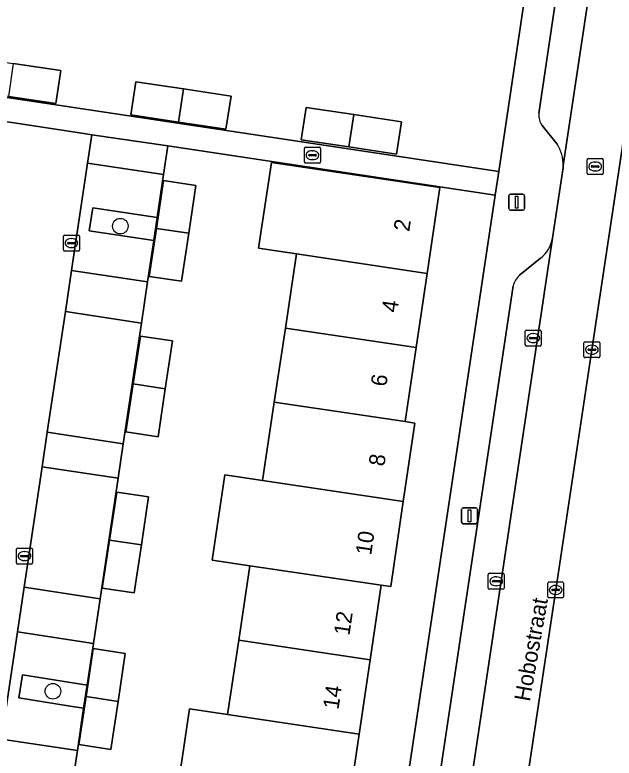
# Model space of a CAD drawing. Extents: x 164148 to 165261, y 382513 to 383432.
# Drawn here: x 164347.95 to 164385.58, y 382801.38 to 382848.02 of the extents above; entities that cross this region are included whole.
import ezdxf

# ---------------------------------------------------------------- set-up
doc = ezdxf.new("R2010")
doc.units = 0
for name, color, linetype in [('IMGEO_Boom', 7, 'Continuous'), ('IMGEO_Erf', 7, 'Continuous'), ('IMGEO_Groenvoorziening', 7, 'Continuous'), ('IMGEO_Kolk', 7, 'Continuous'), ('IMGEO_Lichtmast', 7, 'Continuous'), ('IMGEO_Openbare_ruimte_label', 7, 'Continuous'), ('IMGEO_Pand', 7, 'Continuous'), ('IMGEO_Pand_nummerreeks', 7, 'Continuous'), ('IMGEO_Parkeervlak_open', 7, 'Continuous'), ('IMGEO_Rijbaan_lokaal_open', 7, 'Continuous'), ('IMGEO_Rioolput', 7, 'Continuous'), ('IMGEO_Voetpad_open', 7, 'Continuous')]:
    doc.layers.add(name, color=color, linetype=linetype)

msp = doc.modelspace()

# ---------------------------------------------------------------- linework, layer by layer
at = {"layer": 'IMGEO_Boom'}
for centre in [(164354.574, 382834.763), (164350.346, 382805.576)]:
    msp.add_circle(centre, 0.489, dxfattribs=at)
at = {"layer": 'IMGEO_Erf'}
for points in [[(164380.889, 382859.124), (164325.776, 382867.343), (164325.126, 382866.898), (164322.133, 382846.618), (164350.25, 382842.417), (164378.331, 382838.195), (164381.369, 382858.602)], [(164350.836, 382844.524), (164350.517, 382842.454), (164347.545, 382842.897), (164344.545, 382843.344), (164344.866, 382845.407), (164347.851, 382844.966)], [(164358.537, 382843.372), (164361.525, 382842.923), (164361.208, 382840.852), (164358.225, 382841.297), (164355.24, 382841.743), (164355.548, 382843.82)], [(164369.229, 382841.763), (164372.219, 382841.312), (164371.913, 382839.285), (164368.923, 382839.736), (164365.932, 382840.187), (164366.238, 382842.214)], [(164356.395, 382831.608), (164356.846, 382834.625), (164357.294, 382837.621), (164359.324, 382837.325), (164358.868, 382834.319), (164358.411, 382831.312)], [(164354.92, 382821.853), (164355.381, 382824.867), (164355.84, 382827.87), (164357.858, 382827.572), (164357.4, 382824.56), (164356.942, 382821.548)], [(164353.44, 382812.046), (164353.894, 382815.063), (164354.347, 382818.074), (164356.353, 382817.767), (164355.903, 382814.762), (164355.453, 382811.757)], [(164351.964, 382802.238), (164352.421, 382805.243), (164352.878, 382808.248), (164354.887, 382807.937), (164354.43, 382804.937), (164353.971, 382801.923)]]:
    msp.add_lwpolyline(points, close=True, dxfattribs=at)
for points in [[(164364.8, 382747.97), (164378.11, 382836.71), (164357.562, 382839.799), (164357.294, 382838.011), (164356.888, 382835.303), (164356.672, 382833.86), (164356.285, 382831.275), (164355.896, 382828.681), (164354.761, 382821.108), (164354.436, 382818.942), (164353.301, 382811.365), (164352.883, 382808.572), (164352.49, 382805.954), (164352.274, 382804.514), (164351.878, 382801.866), (164351.47, 382799.147)], [(164358.116, 382799.103), (164358.921, 382804.468), (164361.307, 382804.11), (164362.007, 382808.775), (164362.706, 382813.439), (164360.331, 382813.796), (164361.136, 382819.166), (164363.508, 382818.81), (164364.243, 382823.711), (164364.941, 382828.365), (164365.64, 382833.027), (164363.251, 382833.385), (164364.056, 382838.755), (164374.643, 382837.187), (164373.845, 382831.798), (164373.156, 382827.148), (164372.467, 382822.499), (164373.071, 382822.41), (164372.341, 382817.484), (164371.55, 382812.142), (164370.946, 382812.231), (164370.251, 382807.538), (164369.56, 382802.872), (164368.765, 382797.504)]]:
    msp.add_lwpolyline(points, dxfattribs=at)
at = {"layer": 'IMGEO_Groenvoorziening'}
msp.add_lwpolyline([(164388.653, 382856.791), (164388.469, 382855.564), (164387.957, 382852.16), (164384.178, 382827.011), (164381.905, 382811.932), (164379.997, 382799.194), (164379.527, 382795.989), (164377.081, 382779.734), (164374.497, 382762.461), (164372.688, 382750.223), (164377.348, 382749.559)], dxfattribs=at)
for points in [[(164356.888, 382835.303), (164352.851, 382835.923), (164352.609, 382834.466), (164356.672, 382833.86)], [(164352.49, 382805.954), (164348.44, 382806.605), (164348.214, 382805.152), (164351.421, 382804.648), (164352.274, 382804.514)]]:
    msp.add_lwpolyline(points, close=True, dxfattribs=at)
at = {"layer": 'IMGEO_Kolk'}
for p, q in [((164366.213, 382839.717), (164367.065, 382839.717)), ((164366.138, 382838.791), (164366.138, 382839.643)), ((164366.397, 382839.211), (164366.397, 382839.223)), ((164366.44, 382839.26), (164366.838, 382839.26)), ((164366.626, 382839.497), (164366.651, 382839.497)), ((164366.881, 382839.223), (164366.881, 382839.211)), ((164367.139, 382839.643), (164367.139, 382838.791)), ((164366.835, 382839.174), (164366.437, 382839.174)), ((164366.649, 382838.937), (164366.624, 382838.937)), ((164367.065, 382838.717), (164366.213, 382838.717)), ((164351.003, 382833.274), (164351.003, 382834.126)), ((164351.078, 382834.2), (164351.93, 382834.2)), ((164352.004, 382834.126), (164352.004, 382833.274)), ((164351.262, 382833.694), (164351.262, 382833.706)), ((164351.7, 382833.657), (164351.302, 382833.657)), ((164351.305, 382833.743), (164351.703, 382833.743)), ((164351.491, 382833.98), (164351.516, 382833.98)), ((164351.746, 382833.706), (164351.746, 382833.694)), ((164351.93, 382833.2), (164351.078, 382833.2)), ((164351.514, 382833.42), (164351.489, 382833.42)), ((164379.999, 382827.315), (164379.999, 382828.167)), ((164380.074, 382828.241), (164380.926, 382828.241)), ((164380.487, 382828.021), (164380.512, 382828.021)), ((164381, 382828.167), (164381, 382827.315)), ((164380.258, 382827.735), (164380.258, 382827.747)), ((164380.696, 382827.698), (164380.298, 382827.698)), ((164380.301, 382827.784), (164380.699, 382827.784)), ((164380.742, 382827.747), (164380.742, 382827.735)), ((164380.926, 382827.241), (164380.074, 382827.241)), ((164380.51, 382827.461), (164380.485, 382827.461)), ((164383.677, 382826.585), (164383.677, 382827.437)), ((164383.752, 382827.511), (164384.604, 382827.511)), ((164384.165, 382827.291), (164384.19, 382827.291)), ((164384.678, 382827.437), (164384.678, 382826.585)), ((164383.936, 382827.005), (164383.936, 382827.017)), ((164384.374, 382826.968), (164383.976, 382826.968)), ((164383.979, 382827.054), (164384.377, 382827.054)), ((164384.188, 382826.731), (164384.163, 382826.731)), ((164384.42, 382827.017), (164384.42, 382827.005)), ((164384.604, 382826.511), (164383.752, 382826.511)), ((164348.058, 382813.633), (164348.058, 382814.485)), ((164348.133, 382814.559), (164348.985, 382814.559)), ((164349.059, 382814.485), (164349.059, 382813.633)), ((164348.317, 382814.053), (164348.317, 382814.065)), ((164348.755, 382814.016), (164348.357, 382814.016)), ((164348.36, 382814.102), (164348.758, 382814.102)), ((164348.546, 382814.339), (164348.571, 382814.339)), ((164348.801, 382814.065), (164348.801, 382814.053)), ((164348.985, 382813.559), (164348.133, 382813.559)), ((164348.569, 382813.779), (164348.544, 382813.779)), ((164377.671, 382812.05), (164377.671, 382812.902)), ((164377.746, 382812.976), (164378.598, 382812.976)), ((164378.159, 382812.756), (164378.184, 382812.756)), ((164378.672, 382812.902), (164378.672, 382812.05)), ((164377.93, 382812.47), (164377.93, 382812.482)), ((164378.368, 382812.433), (164377.97, 382812.433)), ((164377.973, 382812.519), (164378.371, 382812.519)), ((164378.182, 382812.196), (164378.157, 382812.196)), ((164378.414, 382812.482), (164378.414, 382812.47)), ((164381.404, 382811.506), (164381.404, 382812.358)), ((164381.479, 382812.432), (164382.331, 382812.432)), ((164381.892, 382812.212), (164381.917, 382812.212)), ((164382.405, 382812.358), (164382.405, 382811.506)), ((164378.598, 382811.976), (164377.746, 382811.976)), ((164381.663, 382811.926), (164381.663, 382811.938)), ((164382.101, 382811.889), (164381.703, 382811.889)), ((164381.706, 382811.975), (164382.104, 382811.975)), ((164382.147, 382811.938), (164382.147, 382811.926)), ((164382.331, 382811.432), (164381.479, 382811.432)), ((164381.915, 382811.652), (164381.89, 382811.652))]:
    msp.add_line(p, q, dxfattribs=at)
for points in [[(164366.213, 382839.717), (164367.065, 382839.717)], [(164366.138, 382838.791), (164366.138, 382839.643)], [(164367.139, 382839.643), (164367.139, 382838.791)], [(164367.065, 382838.717), (164366.213, 382838.717)], [(164351.003, 382833.274), (164351.003, 382834.126)], [(164351.078, 382834.2), (164351.93, 382834.2)], [(164352.004, 382834.126), (164352.004, 382833.274)], [(164351.93, 382833.2), (164351.078, 382833.2)], [(164379.999, 382827.315), (164379.999, 382828.167)], [(164380.074, 382828.241), (164380.926, 382828.241)], [(164381, 382828.167), (164381, 382827.315)], [(164380.926, 382827.241), (164380.074, 382827.241)], [(164383.677, 382826.585), (164383.677, 382827.437)], [(164383.752, 382827.511), (164384.604, 382827.511)], [(164384.678, 382827.437), (164384.678, 382826.585)], [(164384.604, 382826.511), (164383.752, 382826.511)], [(164348.058, 382813.633), (164348.058, 382814.485)], [(164348.133, 382814.559), (164348.985, 382814.559)], [(164349.059, 382814.485), (164349.059, 382813.633)], [(164348.985, 382813.559), (164348.133, 382813.559)], [(164377.671, 382812.05), (164377.671, 382812.902)], [(164377.746, 382812.976), (164378.598, 382812.976)], [(164378.672, 382812.902), (164378.672, 382812.05)], [(164381.404, 382811.506), (164381.404, 382812.358)], [(164381.479, 382812.432), (164382.331, 382812.432)], [(164382.405, 382812.358), (164382.405, 382811.506)], [(164378.598, 382811.976), (164377.746, 382811.976)], [(164382.331, 382811.432), (164381.479, 382811.432)]]:
    msp.add_lwpolyline(points, dxfattribs=at)
for centre, radius, start, end in [((164366.215, 382839.641), 0.0765, 91.552, 178.448), ((164366.215, 382839.641), 0.0765, 91.552, 178.448), ((164367.063, 382839.641), 0.0765, 1.552, 88.448), ((164367.063, 382839.641), 0.0765, 1.552, 88.448), ((164366.437, 382839.22), 0.0403, 85.8775, 175.7526), ((164366.434, 382839.21), 0.0366, 178.938, 274.7102), ((164366.838, 382839.217), 0.043, 264.8664, 352.4533), ((164366.842, 382839.222), 0.0386, 1.7309, 96.639), ((164366.215, 382838.793), 0.0765, 181.552, 268.448), ((164366.215, 382838.793), 0.0765, 181.552, 268.448), ((164367.063, 382838.793), 0.0765, 271.552, 358.448), ((164367.063, 382838.793), 0.0765, 271.552, 358.448), ((164351.08, 382834.124), 0.0765, 91.552, 178.448), ((164351.08, 382834.124), 0.0765, 91.552, 178.448), ((164351.928, 382834.124), 0.0765, 1.552, 88.448), ((164351.928, 382834.124), 0.0765, 1.552, 88.448), ((164351.302, 382833.703), 0.0403, 85.8775, 175.7526), ((164351.299, 382833.693), 0.0366, 178.938, 274.7102), ((164351.703, 382833.7), 0.043, 264.8664, 352.4533), ((164351.707, 382833.705), 0.0386, 1.7309, 96.639), ((164351.08, 382833.276), 0.0765, 181.552, 268.448), ((164351.08, 382833.276), 0.0765, 181.552, 268.448), ((164351.928, 382833.276), 0.0765, 271.552, 358.448), ((164351.928, 382833.276), 0.0765, 271.552, 358.448), ((164380.076, 382828.165), 0.0765, 91.552, 178.448), ((164380.076, 382828.165), 0.0765, 91.552, 178.448), ((164380.924, 382828.165), 0.0765, 1.552, 88.448), ((164380.924, 382828.165), 0.0765, 1.552, 88.448), ((164380.298, 382827.744), 0.0403, 85.8775, 175.7526), ((164380.295, 382827.734), 0.0366, 178.938, 274.7102), ((164380.699, 382827.741), 0.043, 264.8664, 352.4533), ((164380.703, 382827.746), 0.0386, 1.7309, 96.639), ((164380.076, 382827.317), 0.0765, 181.552, 268.448), ((164380.076, 382827.317), 0.0765, 181.552, 268.448), ((164380.924, 382827.317), 0.0765, 271.552, 358.448), ((164380.924, 382827.317), 0.0765, 271.552, 358.448), ((164383.754, 382827.435), 0.0765, 91.552, 178.448), ((164383.754, 382827.435), 0.0765, 91.552, 178.448), ((164384.602, 382827.435), 0.0765, 1.552, 88.448), ((164384.602, 382827.435), 0.0765, 1.552, 88.448), ((164383.976, 382827.014), 0.0403, 85.8775, 175.7526), ((164383.973, 382827.004), 0.0366, 178.938, 274.7102), ((164384.377, 382827.011), 0.043, 264.8664, 352.4533), ((164384.381, 382827.016), 0.0386, 1.7309, 96.639), ((164383.754, 382826.587), 0.0765, 181.552, 268.448), ((164383.754, 382826.587), 0.0765, 181.552, 268.448), ((164384.602, 382826.587), 0.0765, 271.552, 358.448), ((164384.602, 382826.587), 0.0765, 271.552, 358.448), ((164348.135, 382814.483), 0.0765, 91.552, 178.448), ((164348.135, 382814.483), 0.0765, 91.552, 178.448), ((164348.983, 382814.483), 0.0765, 1.552, 88.448), ((164348.983, 382814.483), 0.0765, 1.552, 88.448), ((164348.357, 382814.062), 0.0403, 85.8775, 175.7526), ((164348.354, 382814.052), 0.0366, 178.938, 274.7102), ((164348.758, 382814.059), 0.043, 264.8664, 352.4533), ((164348.762, 382814.064), 0.0386, 1.7309, 96.639), ((164348.135, 382813.635), 0.0765, 181.552, 268.448), ((164348.135, 382813.635), 0.0765, 181.552, 268.448), ((164348.983, 382813.635), 0.0765, 271.552, 358.448), ((164348.983, 382813.635), 0.0765, 271.552, 358.448), ((164377.748, 382812.9), 0.0765, 91.552, 178.448), ((164377.748, 382812.9), 0.0765, 91.552, 178.448), ((164378.596, 382812.9), 0.0765, 1.552, 88.448), ((164378.596, 382812.9), 0.0765, 1.552, 88.448), ((164377.97, 382812.479), 0.0403, 85.8775, 175.7526), ((164377.967, 382812.469), 0.0366, 178.938, 274.7102), ((164378.371, 382812.476), 0.043, 264.8664, 352.4533), ((164378.375, 382812.481), 0.0386, 1.7309, 96.639), ((164381.481, 382812.356), 0.0765, 91.552, 178.448), ((164381.481, 382812.356), 0.0765, 91.552, 178.448), ((164382.329, 382812.356), 0.0765, 1.552, 88.448), ((164382.329, 382812.356), 0.0765, 1.552, 88.448), ((164377.748, 382812.052), 0.0765, 181.552, 268.448), ((164377.748, 382812.052), 0.0765, 181.552, 268.448), ((164378.596, 382812.052), 0.0765, 271.552, 358.448), ((164378.596, 382812.052), 0.0765, 271.552, 358.448), ((164381.703, 382811.935), 0.0403, 85.8775, 175.7526), ((164381.7, 382811.925), 0.0366, 178.938, 274.7102), ((164382.104, 382811.932), 0.043, 264.8664, 352.4533), ((164382.108, 382811.937), 0.0386, 1.7309, 96.639), ((164381.481, 382811.508), 0.0765, 181.552, 268.448), ((164381.481, 382811.508), 0.0765, 181.552, 268.448), ((164382.329, 382811.508), 0.0765, 271.552, 358.448), ((164382.329, 382811.508), 0.0765, 271.552, 358.448)]:
    msp.add_arc(centre, radius, start, end, dxfattribs=at)
for centre, major_axis, ratio, start_param, end_param in [((164366.625, 382839.217), (-0.387, 0.002), 0.722429, 4.712389, 7.853982), ((164366.65, 382839.217), (-0.39, 0.002), 0.717154, 1.570796, 4.712389), ((164351.49, 382833.7), (-0.387, 0.002), 0.722429, 4.712389, 7.853982), ((164351.515, 382833.7), (-0.39, 0.002), 0.717154, 1.570796, 4.712389), ((164380.486, 382827.741), (-0.387, 0.002), 0.722429, 4.712389, 7.853982), ((164380.511, 382827.741), (-0.39, 0.002), 0.717154, 1.570796, 4.712389), ((164384.164, 382827.011), (-0.387, 0.002), 0.722429, 4.712389, 7.853982), ((164384.189, 382827.011), (-0.39, 0.002), 0.717154, 1.570796, 4.712389), ((164348.545, 382814.059), (-0.387, 0.002), 0.722429, 4.712389, 7.853982), ((164348.57, 382814.059), (-0.39, 0.002), 0.717154, 1.570796, 4.712389), ((164378.158, 382812.476), (-0.387, 0.002), 0.722429, 4.712389, 7.853982), ((164378.183, 382812.476), (-0.39, 0.002), 0.717154, 1.570796, 4.712389), ((164381.891, 382811.932), (-0.387, 0.002), 0.722429, 4.712389, 7.853982), ((164381.916, 382811.932), (-0.39, 0.002), 0.717154, 1.570796, 4.712389)]:
    msp.add_ellipse(centre, major_axis=major_axis, ratio=ratio, start_param=start_param, end_param=end_param, dxfattribs=at)
at = {"layer": 'IMGEO_Lichtmast'}
for p, q in [((164378.962, 382835.862), (164378.962, 382836.662)), ((164378.962, 382836.662), (164378.962, 382835.862)), ((164379.062, 382836.762), (164379.852, 382836.762)), ((164379.852, 382836.762), (164379.062, 382836.762)), ((164379.952, 382836.662), (164379.952, 382835.862)), ((164379.952, 382835.862), (164379.952, 382836.662)), ((164379.852, 382835.762), (164379.062, 382835.762)), ((164379.062, 382835.762), (164379.852, 382835.762)), ((164375.999, 382816.187), (164375.999, 382816.987)), ((164375.999, 382816.987), (164375.999, 382816.187)), ((164376.099, 382817.087), (164376.889, 382817.087)), ((164376.889, 382817.087), (164376.099, 382817.087)), ((164376.989, 382816.987), (164376.989, 382816.187)), ((164376.989, 382816.187), (164376.989, 382816.987)), ((164376.889, 382816.087), (164376.099, 382816.087)), ((164376.099, 382816.087), (164376.889, 382816.087))]:
    msp.add_line(p, q, dxfattribs=at)
for points in [[(164379.382, 382836.637), (164379.532, 382836.637), (164379.532, 382835.887), (164379.382, 382835.887), (164379.382, 382836.637)], [(164376.419, 382816.962), (164376.569, 382816.962), (164376.569, 382816.212), (164376.419, 382816.212), (164376.419, 382816.962)]]:
    msp.add_lwpolyline(points, dxfattribs=at)
for centre, start, end in [((164379.062, 382836.662), 90, 180), ((164379.062, 382836.662), 90, 180), ((164379.852, 382836.662), 0, 90), ((164379.852, 382836.662), 360, 90), ((164379.062, 382835.862), 180, 270), ((164379.062, 382835.862), 180, 270), ((164379.852, 382835.862), 270, 0), ((164379.852, 382835.862), 270, 0), ((164376.099, 382816.987), 90, 180), ((164376.099, 382816.987), 90, 180), ((164376.889, 382816.987), 0, 90), ((164376.889, 382816.987), 360, 90), ((164376.099, 382816.187), 180, 270), ((164376.099, 382816.187), 180, 270), ((164376.889, 382816.187), 270, 0), ((164376.889, 382816.187), 270, 0)]:
    msp.add_arc(centre, 0.1, start, end, dxfattribs=at)
at = {"layer": 'IMGEO_Pand'}
for points in [[(164350.836, 382844.524), (164347.851, 382844.966), (164347.545, 382842.897), (164350.517, 382842.454)], [(164358.537, 382843.372), (164355.548, 382843.82), (164355.24, 382841.743), (164358.225, 382841.297)], [(164361.525, 382842.923), (164358.537, 382843.372), (164358.225, 382841.297), (164361.208, 382840.852)], [(164369.229, 382841.763), (164366.238, 382842.214), (164365.932, 382840.187), (164368.923, 382839.736)], [(164372.219, 382841.312), (164369.229, 382841.763), (164368.923, 382839.736), (164371.913, 382839.285)], [(164374.643, 382837.187), (164364.056, 382838.755), (164363.251, 382833.385), (164365.64, 382833.027), (164373.845, 382831.798)], [(164359.324, 382837.325), (164357.294, 382837.621), (164356.846, 382834.625), (164358.868, 382834.319)], [(164358.868, 382834.319), (164356.846, 382834.625), (164356.395, 382831.608), (164358.411, 382831.312)], [(164373.845, 382831.798), (164365.64, 382833.027), (164364.941, 382828.365), (164373.156, 382827.148)], [(164373.156, 382827.148), (164364.941, 382828.365), (164364.243, 382823.711), (164372.467, 382822.499)], [(164357.858, 382827.572), (164355.84, 382827.87), (164355.381, 382824.867), (164357.4, 382824.56)], [(164357.4, 382824.56), (164355.381, 382824.867), (164354.92, 382821.853), (164356.942, 382821.548)], [(164373.071, 382822.41), (164372.467, 382822.499), (164364.243, 382823.711), (164363.508, 382818.81), (164372.341, 382817.484)], [(164372.341, 382817.484), (164363.508, 382818.81), (164361.136, 382819.166), (164360.331, 382813.796), (164362.706, 382813.439), (164370.946, 382812.231), (164371.55, 382812.142)], [(164356.353, 382817.767), (164354.347, 382818.074), (164353.894, 382815.063), (164355.903, 382814.762)], [(164355.903, 382814.762), (164353.894, 382815.063), (164353.44, 382812.046), (164355.453, 382811.757)], [(164370.946, 382812.231), (164362.706, 382813.439), (164362.007, 382808.775), (164370.251, 382807.538)], [(164370.251, 382807.538), (164362.007, 382808.775), (164361.307, 382804.11), (164369.56, 382802.872)], [(164352.878, 382808.248), (164352.421, 382805.243), (164354.43, 382804.937), (164354.887, 382807.937)], [(164354.43, 382804.937), (164352.421, 382805.243), (164351.964, 382802.238), (164353.971, 382801.923)], [(164369.56, 382802.872), (164361.307, 382804.11), (164358.921, 382804.468), (164358.116, 382799.103), (164360.493, 382798.746), (164368.765, 382797.504)]]:
    msp.add_lwpolyline(points, close=True, dxfattribs=at)
at = {"layer": 'IMGEO_Parkeervlak_open'}
for points in [[(164382.377, 382838.563), (164385.018, 382856.097)], [(164382.615, 382853.697), (164380.849, 382841.827)], [(164381.049, 382841.077), (164381.999, 382839.912)], [(164377.452, 382805.647), (164381.703, 382834.004)], [(164380.962, 382832.756), (164379.639, 382831.691)], [(164379.235, 382831.014), (164367.98, 382755.927)], [(164369.459, 382752.322), (164377.452, 382805.647)]]:
    msp.add_lwpolyline(points, dxfattribs=at)
for points in [[(164356.672, 382833.86), (164352.609, 382834.466), (164352.851, 382835.923), (164356.888, 382835.303), (164357.294, 382838.011), (164352.523, 382838.717), (164351.515, 382831.984), (164356.285, 382831.275)], [(164355.896, 382828.681), (164351.128, 382829.402), (164349.993, 382821.825), (164354.761, 382821.108)], [(164354.436, 382818.942), (164349.669, 382819.657), (164348.538, 382812.111), (164353.301, 382811.365)], [(164352.274, 382804.514), (164351.421, 382804.648), (164348.214, 382805.152), (164348.44, 382806.605), (164352.49, 382805.954), (164352.883, 382808.572), (164348.119, 382809.31), (164347.108, 382802.559), (164351.878, 382801.866)]]:
    msp.add_lwpolyline(points, close=True, dxfattribs=at)
for centre, radius, start, end in [((164381.95, 382841.719), 1.107, 174.4014, 215.4614), ((164380.071, 382838.644), 2.307, 357.9806, 33.3259), ((164379.679, 382834.362), 2.055, 308.6221, 349.9784), ((164380.647, 382830.631), 1.463, 133.542, 164.8047)]:
    msp.add_arc(centre, radius, start, end, dxfattribs=at)
at = {"layer": 'IMGEO_Rijbaan_lokaal_open'}
msp.add_lwpolyline([(164377.081, 382779.734), (164379.527, 382795.989), (164379.997, 382799.194), (164381.905, 382811.932), (164384.178, 382827.011), (164387.957, 382852.16), (164388.469, 382855.564), (164385.018, 382856.097), (164382.377, 382838.563), (164382.368, 382838.422), (164382.245, 382837.606), (164381.703, 382834.004), (164377.452, 382805.647), (164369.459, 382752.322), (164369.209, 382750.719), (164372.688, 382750.223), (164374.497, 382762.461)], close=True, dxfattribs=at)
msp.add_lwpolyline([(164346.706, 382799.875), (164347.108, 382802.559), (164348.119, 382809.31), (164348.538, 382812.111), (164349.669, 382819.657), (164349.993, 382821.825), (164351.128, 382829.402), (164351.515, 382831.984), (164352.523, 382838.717), (164352.791, 382840.504), (164352.276, 382840.585), (164347.755, 382841.26), (164347.238, 382841.326), (164347.039, 382839.997), (164345.904, 382832.423), (164345.486, 382829.632), (164344.474, 382822.879), (164344.073, 382820.206), (164342.967, 382812.827), (164342.629, 382810.568), (164341.49, 382802.969), (164341.089, 382800.293)], dxfattribs=at)
at = {"layer": 'IMGEO_Rioolput'}
for p, q in [((164383.884, 382838.084), (164383.884, 382838.936)), ((164383.959, 382839.01), (164384.811, 382839.01)), ((164384.372, 382838.79), (164384.397, 382838.79)), ((164384.885, 382838.936), (164384.885, 382838.084)), ((164384.143, 382838.504), (164384.143, 382838.516)), ((164384.581, 382838.467), (164384.183, 382838.467)), ((164384.186, 382838.553), (164384.584, 382838.553)), ((164384.627, 382838.516), (164384.627, 382838.504)), ((164384.811, 382838.01), (164383.959, 382838.01)), ((164384.395, 382838.23), (164384.37, 382838.23))]:
    msp.add_line(p, q, dxfattribs=at)
for points in [[(164383.884, 382838.084), (164383.884, 382838.936)], [(164383.959, 382839.01), (164384.811, 382839.01)], [(164384.885, 382838.936), (164384.885, 382838.084)], [(164384.811, 382838.01), (164383.959, 382838.01)]]:
    msp.add_lwpolyline(points, dxfattribs=at)
for centre, radius, start, end in [((164383.961, 382838.934), 0.0765, 91.552, 178.448), ((164383.961, 382838.934), 0.0765, 91.552, 178.448), ((164384.809, 382838.934), 0.0765, 1.552, 88.448), ((164384.809, 382838.934), 0.0765, 1.552, 88.448), ((164384.183, 382838.513), 0.0403, 85.8775, 175.7526), ((164384.18, 382838.503), 0.0366, 178.938, 274.7102), ((164384.584, 382838.51), 0.043, 264.8664, 352.4533), ((164384.588, 382838.515), 0.0386, 1.7309, 96.639), ((164383.961, 382838.086), 0.0765, 181.552, 268.448), ((164383.961, 382838.086), 0.0765, 181.552, 268.448), ((164384.809, 382838.086), 0.0765, 271.552, 358.448), ((164384.809, 382838.086), 0.0765, 271.552, 358.448)]:
    msp.add_arc(centre, radius, start, end, dxfattribs=at)
for centre, major_axis, ratio, start_param, end_param in [((164384.371, 382838.51), (-0.387, 0.002), 0.722429, 4.712389, 7.853982), ((164384.396, 382838.51), (-0.39, 0.002), 0.717154, 1.570796, 4.712389)]:
    msp.add_ellipse(centre, major_axis=major_axis, ratio=ratio, start_param=start_param, end_param=end_param, dxfattribs=at)
at = {"layer": 'IMGEO_Voetpad_open'}
for points in [[(164385.178, 382859.221), (164380.889, 382859.124), (164381.369, 382858.602), (164378.331, 382838.195), (164378.11, 382836.71), (164364.8, 382747.97), (164366.42, 382745.631)], [(164380.849, 382841.827), (164382.615, 382853.697)], [(164381.999, 382839.912), (164381.049, 382841.077)], [(164381.703, 382834.004), (164382.245, 382837.606), (164382.368, 382838.422), (164382.377, 382838.563)], [(164379.639, 382831.691), (164380.962, 382832.756)], [(164367.98, 382755.927), (164379.235, 382831.014)]]:
    msp.add_lwpolyline(points, dxfattribs=at)
for points in [[(164350.25, 382842.417), (164322.133, 382846.618), (164321.904, 382845.071), (164342.463, 382842.062), (164347.238, 382841.326), (164347.755, 382841.26), (164352.276, 382840.585), (164352.791, 382840.504), (164357.562, 382839.799), (164378.11, 382836.71), (164378.331, 382838.195)], [(164357.562, 382839.799), (164352.791, 382840.504), (164352.523, 382838.717), (164357.294, 382838.011)], [(164356.285, 382831.275), (164351.515, 382831.984), (164351.128, 382829.402), (164355.896, 382828.681)], [(164354.761, 382821.108), (164349.993, 382821.825), (164349.669, 382819.657), (164354.436, 382818.942)], [(164353.301, 382811.365), (164348.538, 382812.111), (164348.119, 382809.31), (164352.883, 382808.572)], [(164351.878, 382801.866), (164347.108, 382802.559), (164346.706, 382799.875), (164351.47, 382799.147)]]:
    msp.add_lwpolyline(points, close=True, dxfattribs=at)
for centre, radius, start, end in [((164381.95, 382841.719), 1.107, 174.4014, 215.4614), ((164380.071, 382838.644), 2.307, 357.9806, 33.3259), ((164379.679, 382834.362), 2.055, 308.6221, 349.9784), ((164380.647, 382830.631), 1.463, 133.542, 164.8047)]:
    msp.add_arc(centre, radius, start, end, dxfattribs=at)

# ---------------------------------------------------------------- texts
at = {"layer": 'IMGEO_Openbare_ruimte_label'}
msp.add_text('Hobostraat', height=1, rotation=79.9821, dxfattribs=at).set_placement((164380.284, 382804.892))
msp.add_text('Hobostraat', height=1, rotation=79.9821, dxfattribs=at).set_placement((164380.284, 382804.892))
at = {"layer": 'IMGEO_Pand_nummerreeks'}
for s, p in [('2', (164372.712, 382834.389)), ('4', (164371.96, 382829.307)), ('6', (164371.271, 382824.66)), ('8', (164371.147, 382819.656)), ('10', (164370.32, 382814.08)), ('12', (164368.956, 382809.038)), ('14', (164368.269, 382804.398))]:
    msp.add_text(s, height=1, rotation=81.572, dxfattribs=at).set_placement(p)

doc.saveas('drawing.dxf')
